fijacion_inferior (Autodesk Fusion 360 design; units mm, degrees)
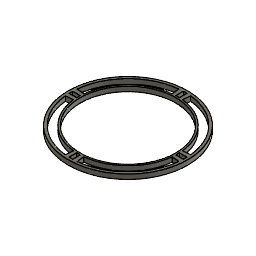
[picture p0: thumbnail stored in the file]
part number: 2026-07-13-18-41-32-936
sketch "Boceto" plane through (0, 0, 0) normal (0, 1, 0) x axis (1, 0, 0)
  line L1 (41.5, -1.5) -> (47.25, -1.5)
  line L2 (41.5, 0) -> (41.5, -1.5)
  line L3 (41.5, 1.5) -> (47.25, 1.5)
  line L4 (41.5, 0) -> (41.5, 1.5)
  line L5 (-1.5, 41.5) -> (-1.5, 47.25)
  line L6 (0, 41.5) -> (-1.5, 41.5)
  line L7 (0, 41.5) -> (1.5, 41.5)
  line L8 (1.5, 41.5) -> (1.5, 47.25)
  line L9 (-41.5, -1.5) -> (-47.25, -1.5)
  line L10 (-41.5, 0) -> (-41.5, -1.5)
  line L11 (-41.5, 0) -> (-41.5, 1.5)
  line L12 (-41.5, 1.5) -> (-47.25, 1.5)
  line L13 (1.5, -41.5) -> (1.5, -47.25)
  line L14 (0, -41.5) -> (1.5, -41.5)
  line L15 (0, -41.5) -> (-1.5, -41.5)
  line L16 (-1.5, -41.5) -> (-1.5, -47.25)
  line L17 (-1.5, 47.7262) -> (-1.5, 47.2262)
  line L18 (1.5, 47.25) -> (1.5, 47.7262)
  line L19 (47.75, 1.5) -> (47.25, 1.5)
  line L20 (47.75, -1.5) -> (47.25, -1.5)
  line L21 (47.75, -1.5) -> (47.75, 1.5)
  line L22 (1.5, -47.75) -> (1.5, -47.25)
  line L23 (-1.5, -47.7262) -> (-1.5, -47.2262)
  line L24 (-47.25, 1.5) -> (-47.2262, 1.5)
  line L25 (-47.75, -1.5) -> (-47.25, -1.5)
  line L26 (-47.75, 1.5) -> (-47.25, 1.5)
  line L27 (-47.75, -1.5) -> (-47.75, 1.5)
  line L28 (1.5, 41.5) -> (1.5, 47.25)
  line L29 (1.5, 47.75) -> (1.5, 47.25)
  line L30 (1.5, 47.75) -> (-1.5, 47.75)
  line L31 (-1.5, 47.75) -> (-1.5, 47.25)
  line L32 (-1.5, 41.5) -> (-1.5, 47.25)
  line L33 (0, 41.5) -> (-1.5, 41.5)
  line L34 (0, 41.5) -> (1.5, 41.5)
  line L35 (-41.5, 1.5) -> (-47.25, 1.5)
  line L36 (-47.75, 1.5) -> (-47.25, 1.5)
  line L37 (-47.75, 1.5) -> (-47.75, -1.5)
  line L38 (-47.75, -1.5) -> (-47.25, -1.5)
  line L39 (-41.5, -1.5) -> (-47.25, -1.5)
  line L40 (-41.5, 0) -> (-41.5, -1.5)
  line L41 (-41.5, 0) -> (-41.5, 1.5)
  line L42 (-1.5, -41.5) -> (-1.5, -47.25)
  line L43 (-1.5, -47.75) -> (-1.5, -47.25)
  line L44 (-1.5, -47.75) -> (1.5, -47.75)
  line L45 (1.5, -47.75) -> (1.5, -47.25)
  line L46 (1.5, -41.5) -> (1.5, -47.25)
  line L47 (0, -41.5) -> (1.5, -41.5)
  line L48 (0, -41.5) -> (-1.5, -41.5)
  line L49 (47.5118, -4.9937) -> (41.2996, -4.3408)
  line L50 (47.7736, 0) -> (0, 0)
  line L51 (47.5118, 4.9937) -> (41.2996, 4.3408)
  line L52 (-4.9937, 47.5118) -> (-4.3408, 41.2996)
  line L53 (4.9937, 47.5118) -> (4.3408, 41.2996)
  line L54 (-47.5118, -4.9937) -> (-41.2996, -4.3408)
  line L55 (-47.5118, 4.9937) -> (-41.2996, 4.3408)
  line L56 (4.9937, -47.5118) -> (4.3408, -41.2996)
  line L57 (-4.9937, -47.5118) -> (-4.3408, -41.2996)
  circle C1 centre (0, 0) radius 50
  circle C2 centre (0, 0) radius 40
  arc A1 centre (0, 0) radius 47.7736 clockwise from (47.5118, -4.9937) to (4.9937, -47.5118)
  arc A2 centre (0, 0) radius 47.7736 clockwise from (-4.9937, -47.5118) to (-47.5118, -4.9937)
  arc A3 centre (0, 0) radius 41.5271 clockwise from (4.3408, 41.2996) to (41.2996, 4.3408)
  arc A4 centre (0, 0) radius 41.5271 clockwise from (-41.2996, 4.3408) to (-4.3408, 41.2996)
  arc A5 centre (0, 0) radius 47.7736 clockwise from (4.9937, 47.5118) to (47.5118, 4.9937)
  arc A6 centre (0, 0) radius 47.7736 clockwise from (-47.5118, 4.9937) to (-4.9937, 47.5118)
  arc A7 centre (0, 0) radius 41.5271 clockwise from (41.2996, -4.3408) to (4.3408, -41.2996)
  arc A8 centre (0, 0) radius 41.5271 clockwise from (-4.3408, -41.2996) to (-41.2996, -4.3408)
  arc A9 centre (0, 0) radius 41.5271 clockwise from (1.5, -41.5) to (-1.5, -41.5)
  point P23 (-1.5, 47.2262)
  point P24 (-47.2262, 1.5)
  point P25 (-1.5, -47.2262)
  point P1 (0, 0)
  point P57 (0, 0)
  point P58 (0, 0)
  point P63 (0, 0)
  point P64 (47.5118, -4.9937)
  point P66 (47.5118, 4.9937)
  point P3 (41.5, 0)
  point P5 (41.5, -1.5)
  point P7 (41.5, 1.5)
  point P27 (-1.5, 47.7262)
  point P6 (47.25, 1.5)
  point P29 (47.75, 1.5)
  point P4 (47.25, -1.5)
  point P30 (47.75, -1.5)
  point P18 (1.5, -47.25)
  point P31 (1.5, -47.75)
  point P32 (-1.5, -47.7262)
  point P13 (-47.25, -1.5)
  point P33 (-47.75, -1.5)
  point P17 (-47.25, 1.5)
  point P34 (-47.75, 1.5)
  horizontal L1
  vertical L2
  horizontal L3
  vertical L4
  coincident L5 P23
  coincident L12 P24
  coincident L16 P25
  perpendicular L20 L21
  perpendicular L25 L27
  concentric C1 A5
  coincident P1 P57
  concentric A1 A5
  concentric A2 A6
  concentric A3 A7
  concentric A3 A4
  concentric A5 A6
  horizontal L50
  coincident P58 P63
  symmetric P64 L50 P66
  concentric A7 A9
  concentric A8 A9
  dimension "d3" diameter C1 = 100
  dimension "d5" distance P3 P5 = 1.5
  dimension "d7" distance P3 P7 = 1.5
  dimension "d10" diameter C2 = 80
  dimension "d13" distance P23 P27 = 0.5
  dimension "d14" distance P6 P29 = 0.5
  dimension "d15" distance P4 P30 = 0.5
  dimension "d16" distance P18 P31 = 0.5
  dimension "d17" distance P25 P32 = 0.5
  dimension "d19" distance P13 P33 = 0.5
  dimension "d21" distance P17 P34 = 0.5
  dimension "d26" angle L49 L50 = 6
  dimension "d23" C-Pattern1-Angle = 360
  dimension "d28" C-Pattern2-Angle = 360
extrude "Extruir" new body sketch "Boceto" profile of C1 L1 L2 L3 L4 L5 L6 L7 L8 L9 L10 L11 L12 L13 L14 L15 L16 C2 L17 L18 L19 L20 L21 L22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 along normal blind 4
